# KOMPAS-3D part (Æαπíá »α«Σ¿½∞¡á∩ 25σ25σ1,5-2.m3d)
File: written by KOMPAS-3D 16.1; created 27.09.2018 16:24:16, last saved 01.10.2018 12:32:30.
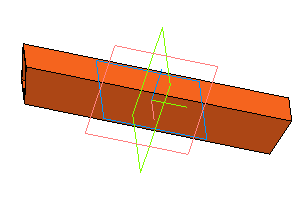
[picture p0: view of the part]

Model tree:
1. Эскиз:1
2. Операция выдавливания:1
     Расстояние 2 = 10
3. Эскиз:2
4. Вырезать элемент выдавливания:1  (labels: А302-01.40.002)
     Расстояние 1 = 20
